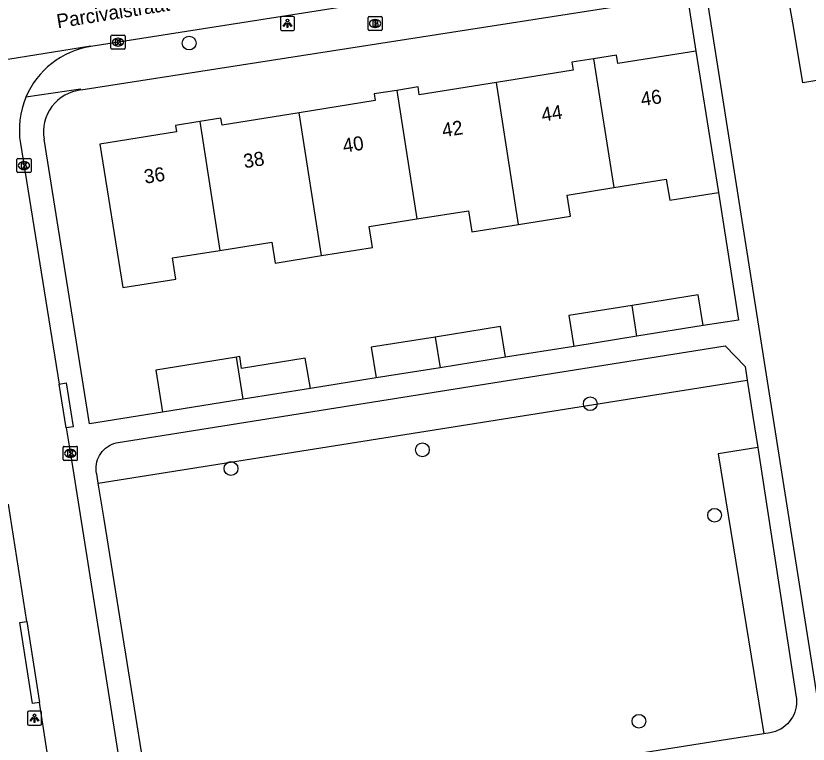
# Model space of a CAD drawing. Extents: x 160077 to 160945, y 386481 to 387498.
# Drawn here: x 160528.9 to 160585.2, y 387094.6 to 387146.3 of the extents above; entities that cross this region are included whole.
import ezdxf

# ---------------------------------------------------------------- set-up
doc = ezdxf.new("R2010")
doc.units = 0
for name, color, linetype in [('IMGEO_Boom', 7, 'Continuous'), ('IMGEO_Brandkraan', 7, 'Continuous'), ('IMGEO_Groenvoorziening', 7, 'Continuous'), ('IMGEO_Kolk', 7, 'Continuous'), ('IMGEO_Lichtpunt', 7, 'Continuous'), ('IMGEO_Openbare_ruimte_label', 7, 'Continuous'), ('IMGEO_Pand', 7, 'Continuous'), ('IMGEO_Pand_nummerreeks', 7, 'Continuous'), ('IMGEO_Rijbaan_lokaal_open', 7, 'Continuous'), ('IMGEO_Voetpad_open', 7, 'Continuous')]:
    doc.layers.add(name, color=color, linetype=linetype)

msp = doc.modelspace()

# ---------------------------------------------------------------- linework, layer by layer
at = {"layer": 'IMGEO_Boom'}
for centre in [(160541.197, 387144.403), (160569.693, 387118.779), (160557.764, 387115.499), (160544.169, 387114.171), (160578.519, 387110.85), (160573.146, 387096.211)]:
    msp.add_circle(centre, 0.489, dxfattribs=at)
at = {"layer": 'IMGEO_Brandkraan'}
for p, q in [((160553.981, 387146.294), (160554.833, 387146.294)), ((160553.906, 387145.368), (160553.906, 387146.22)), ((160554.394, 387146.074), (160554.419, 387146.074)), ((160554.907, 387146.22), (160554.907, 387145.368)), ((160554.833, 387145.294), (160553.981, 387145.294)), ((160554.417, 387145.514), (160554.392, 387145.514))]:
    msp.add_line(p, q, dxfattribs=at)
for points in [[(160553.981, 387146.294), (160554.833, 387146.294)], [(160553.906, 387145.368), (160553.906, 387146.22)], [(160554.254, 387145.994), (160554.254, 387145.594), (160554.467, 387145.594)], [(160554.485, 387145.994), (160554.254, 387145.994)], [(160554.433, 387145.913), (160554.379, 387145.913), (160554.379, 387145.837)], [(160554.379, 387145.837), (160554.432, 387145.837)], [(160554.441, 387145.761), (160554.379, 387145.761), (160554.379, 387145.68)], [(160554.907, 387146.22), (160554.907, 387145.368)], [(160554.833, 387145.294), (160553.981, 387145.294)], [(160554.379, 387145.68), (160554.441, 387145.68)]]:
    msp.add_lwpolyline(points, dxfattribs=at)
for centre, radius, start, end in [((160553.983, 387146.218), 0.0765, 91.552, 178.448), ((160553.983, 387146.218), 0.0765, 91.552, 178.448), ((160554.831, 387146.218), 0.0765, 1.552, 88.448), ((160554.831, 387146.218), 0.0765, 1.552, 88.448), ((160554.434, 387145.875), 0.0379, 267.8285, 90.9355), ((160554.442, 387145.72), 0.0404, 269.8759, 90.5077), ((160554.489, 387145.849), 0.145, 59.4692, 91.5367), ((160554.514, 387145.896), 0.0922, 285.5137, 58.1501), ((160554.519, 387145.704), 0.105, 301.3115, 78.989), ((160553.983, 387145.37), 0.0765, 181.552, 268.448), ((160553.983, 387145.37), 0.0765, 181.552, 268.448), ((160554.473, 387145.845), 0.251, 268.6676, 293.5347), ((160554.831, 387145.37), 0.0765, 271.552, 358.448), ((160554.831, 387145.37), 0.0765, 271.552, 358.448)]:
    msp.add_arc(centre, radius, start, end, dxfattribs=at)
for centre, major_axis, ratio, start_param, end_param in [((160554.393, 387145.794), (-0.387, 0.002), 0.722429, 4.712389, 7.853982), ((160554.418, 387145.794), (-0.39, 0.002), 0.717154, 1.570796, 4.712389)]:
    msp.add_ellipse(centre, major_axis=major_axis, ratio=ratio, start_param=start_param, end_param=end_param, dxfattribs=at)
at = {"layer": 'IMGEO_Groenvoorziening'}
for points in [[(160534.737, 387113.131), (160580.846, 387120.446)], [(160581.584, 387115.663), (160578.776, 387115.218), (160582.014, 387095.328)]]:
    msp.add_lwpolyline(points, dxfattribs=at)
at = {"layer": 'IMGEO_Kolk'}
for p, q in [((160535.642, 387144.042), (160535.642, 387144.894)), ((160535.717, 387144.968), (160536.569, 387144.968)), ((160536.13, 387144.748), (160536.155, 387144.748)), ((160536.643, 387144.894), (160536.643, 387144.042)), ((160536.153, 387144.188), (160536.128, 387144.188)), ((160536.569, 387143.968), (160535.717, 387143.968)), ((160529.037, 387136.199), (160529.889, 387136.199)), ((160528.962, 387135.273), (160528.962, 387136.125)), ((160529.45, 387135.979), (160529.475, 387135.979)), ((160529.963, 387136.125), (160529.963, 387135.273)), ((160529.889, 387135.199), (160529.037, 387135.199)), ((160529.473, 387135.419), (160529.448, 387135.419)), ((160532.253, 387114.822), (160532.253, 387115.674)), ((160532.328, 387115.748), (160533.18, 387115.748)), ((160532.741, 387115.528), (160532.766, 387115.528)), ((160533.254, 387115.674), (160533.254, 387114.822)), ((160533.18, 387114.748), (160532.328, 387114.748)), ((160532.764, 387114.968), (160532.739, 387114.968))]:
    msp.add_line(p, q, dxfattribs=at)
for points in [[(160535.642, 387144.042), (160535.642, 387144.894)], [(160535.717, 387144.968), (160536.569, 387144.968)], [(160535.963, 387144.668), (160536.086, 387144.668), (160536.086, 387144.517), (160536.216, 387144.668), (160536.38, 387144.668), (160536.234, 387144.517), (160536.387, 387144.268), (160536.235, 387144.268), (160536.15, 387144.432), (160536.086, 387144.365), (160536.086, 387144.268), (160535.963, 387144.268), (160535.963, 387144.668)], [(160536.643, 387144.894), (160536.643, 387144.042)], [(160536.569, 387143.968), (160535.717, 387143.968)], [(160529.037, 387136.199), (160529.889, 387136.199)], [(160528.962, 387135.273), (160528.962, 387136.125)], [(160529.283, 387135.899), (160529.406, 387135.899), (160529.406, 387135.748), (160529.536, 387135.899), (160529.7, 387135.899), (160529.554, 387135.748), (160529.707, 387135.499), (160529.555, 387135.499), (160529.47, 387135.663), (160529.406, 387135.596), (160529.406, 387135.499), (160529.283, 387135.499), (160529.283, 387135.899)], [(160529.963, 387136.125), (160529.963, 387135.273)], [(160529.889, 387135.199), (160529.037, 387135.199)], [(160532.253, 387114.822), (160532.253, 387115.674)], [(160532.328, 387115.748), (160533.18, 387115.748)], [(160532.574, 387115.448), (160532.697, 387115.448), (160532.697, 387115.297), (160532.827, 387115.448), (160532.991, 387115.448), (160532.845, 387115.297), (160532.998, 387115.048), (160532.846, 387115.048), (160532.761, 387115.212), (160532.697, 387115.145), (160532.697, 387115.048), (160532.574, 387115.048), (160532.574, 387115.448)], [(160533.254, 387115.674), (160533.254, 387114.822)], [(160533.18, 387114.748), (160532.328, 387114.748)]]:
    msp.add_lwpolyline(points, dxfattribs=at)
for centre, start, end in [((160535.719, 387144.892), 91.552, 178.448), ((160535.719, 387144.892), 91.552, 178.448), ((160536.567, 387144.892), 1.552, 88.448), ((160536.567, 387144.892), 1.552, 88.448), ((160535.719, 387144.044), 181.552, 268.448), ((160535.719, 387144.044), 181.552, 268.448), ((160536.567, 387144.044), 271.552, 358.448), ((160536.567, 387144.044), 271.552, 358.448), ((160529.039, 387136.123), 91.552, 178.448), ((160529.039, 387136.123), 91.552, 178.448), ((160529.887, 387136.123), 1.552, 88.448), ((160529.887, 387136.123), 1.552, 88.448), ((160529.039, 387135.275), 181.552, 268.448), ((160529.039, 387135.275), 181.552, 268.448), ((160529.887, 387135.275), 271.552, 358.448), ((160529.887, 387135.275), 271.552, 358.448), ((160532.33, 387115.672), 91.552, 178.448), ((160532.33, 387115.672), 91.552, 178.448), ((160533.178, 387115.672), 1.552, 88.448), ((160533.178, 387115.672), 1.552, 88.448), ((160532.33, 387114.824), 181.552, 268.448), ((160532.33, 387114.824), 181.552, 268.448), ((160533.178, 387114.824), 271.552, 358.448), ((160533.178, 387114.824), 271.552, 358.448)]:
    msp.add_arc(centre, 0.0765, start, end, dxfattribs=at)
for centre, major_axis, ratio, start_param, end_param in [((160536.129, 387144.468), (-0.387, 0.002), 0.722429, 4.712389, 7.853982), ((160536.154, 387144.468), (-0.39, 0.002), 0.717154, 1.570796, 4.712389), ((160529.449, 387135.699), (-0.387, 0.002), 0.722429, 4.712389, 7.853982), ((160529.474, 387135.699), (-0.39, 0.002), 0.717154, 1.570796, 4.712389), ((160532.74, 387115.248), (-0.387, 0.002), 0.722429, 4.712389, 7.853982), ((160532.765, 387115.248), (-0.39, 0.002), 0.717154, 1.570796, 4.712389)]:
    msp.add_ellipse(centre, major_axis=major_axis, ratio=ratio, start_param=start_param, end_param=end_param, dxfattribs=at)
at = {"layer": 'IMGEO_Lichtpunt'}
for p, q in [((160548.582, 387146.302), (160547.774, 387146.302)), ((160548.582, 387146.302), (160547.774, 387146.302)), ((160547.68, 387146.207), (160547.68, 387145.4)), ((160547.68, 387146.207), (160547.68, 387145.4)), ((160548.676, 387145.4), (160548.676, 387146.207)), ((160548.676, 387145.4), (160548.676, 387146.207)), ((160547.774, 387145.306), (160548.582, 387145.306)), ((160547.774, 387145.306), (160548.582, 387145.306)), ((160529.709, 387096.837), (160529.709, 387096.03)), ((160529.709, 387096.837), (160529.709, 387096.03)), ((160530.611, 387096.932), (160529.803, 387096.932)), ((160530.611, 387096.932), (160529.803, 387096.932)), ((160530.705, 387096.03), (160530.705, 387096.837)), ((160530.705, 387096.03), (160530.705, 387096.837)), ((160529.803, 387095.936), (160530.611, 387095.936)), ((160529.803, 387095.936), (160530.611, 387095.936))]:
    msp.add_line(p, q, dxfattribs=at)
for points in [[(160548.054, 387145.871), (160548.093, 387145.843), (160547.905, 387145.581), (160547.867, 387145.608), (160548.054, 387145.871)], [(160548.156, 387145.823), (160548.203, 387145.823), (160548.203, 387145.501), (160548.156, 387145.501), (160548.156, 387145.823)], [(160548.266, 387145.843), (160548.304, 387145.87), (160548.491, 387145.608), (160548.452, 387145.58), (160548.266, 387145.843)], [(160530.083, 387096.501), (160530.122, 387096.473), (160529.934, 387096.211), (160529.896, 387096.238), (160530.083, 387096.501)], [(160530.185, 387096.453), (160530.232, 387096.453), (160530.232, 387096.131), (160530.185, 387096.131), (160530.185, 387096.453)], [(160530.295, 387096.473), (160530.333, 387096.5), (160530.52, 387096.238), (160530.481, 387096.21), (160530.295, 387096.473)]]:
    msp.add_lwpolyline(points, dxfattribs=at)
for centre in [(160548.179, 387146.005), (160530.208, 387096.635)]:
    msp.add_circle(centre, 0.0994, dxfattribs=at)
for centre, start, end in [((160547.774, 387146.207), 90, 180), ((160547.774, 387146.207), 90, 180), ((160548.582, 387146.207), 0, 90), ((160548.582, 387146.207), 0, 90), ((160547.774, 387145.4), 180, 270), ((160547.774, 387145.4), 180, 270), ((160548.582, 387145.4), 270, 0), ((160548.582, 387145.4), 270, 360), ((160529.803, 387096.837), 90, 180), ((160529.803, 387096.837), 90, 180), ((160530.611, 387096.837), 0, 90), ((160530.611, 387096.837), 0, 90), ((160529.803, 387096.03), 180, 270), ((160529.803, 387096.03), 180, 270), ((160530.611, 387096.03), 270, 0), ((160530.611, 387096.03), 270, 360)]:
    msp.add_arc(centre, 0.0946, start, end, dxfattribs=at)
at = {"layer": 'IMGEO_Pand'}
for points in [[(160589.356, 387138.611), (160588.739, 387142.241), (160584.795, 387141.57), (160584.139, 387145.429), (160583.82, 387147.304), (160592.221, 387148.726), (160592.068, 387149.63), (160597.838, 387150.607), (160598.182, 387148.576), (160598.197, 387148.49), (160597.3, 387148.338), (160597.413, 387147.677), (160597.202, 387147.641), (160597.776, 387144.255), (160600.083, 387144.098), (160600.707, 387140.417)], [(160577.19, 387143.831), (160571.641, 387142.943), (160571.543, 387143.552), (160569.927, 387143.293)], [(160577.19, 387143.831), (160578.799, 387133.783)], [(160569.927, 387143.293), (160568.385, 387143.046), (160568.475, 387142.486), (160563.021, 387141.612)], [(160569.927, 387143.293), (160571.357, 387134.136)], [(160563.021, 387141.612), (160557.546, 387140.735), (160557.458, 387141.284), (160555.942, 387141.041)], [(160564.597, 387131.519), (160563.021, 387141.612)], [(160555.942, 387141.041), (160554.346, 387140.785), (160554.42, 387140.319), (160549.02, 387139.454)], [(160555.942, 387141.041), (160557.368, 387131.906)], [(160549.02, 387139.454), (160543.532, 387138.575), (160543.454, 387139.065), (160541.949, 387138.824)], [(160550.605, 387129.298), (160549.02, 387139.454)], [(160541.949, 387138.824), (160540.233, 387138.549), (160540.306, 387138.093), (160534.855, 387137.22), (160536.486, 387127.037), (160540.247, 387127.636), (160540.008, 387129.138), (160543.378, 387129.675)], [(160541.949, 387138.824), (160543.378, 387129.675)], [(160571.357, 387134.136), (160575.091, 387134.731), (160575.331, 387133.23), (160578.799, 387133.783)], [(160564.597, 387131.519), (160568.278, 387132.105), (160568.039, 387133.607), (160571.357, 387134.136)], [(160557.368, 387131.906), (160561.046, 387132.492), (160561.286, 387130.991), (160564.597, 387131.519)], [(160550.605, 387129.298), (160554.231, 387129.876), (160553.994, 387131.368), (160557.368, 387131.906)], [(160543.378, 387129.675), (160547.06, 387130.262), (160547.298, 387128.771), (160550.605, 387129.298)], [(160577.698, 387124.323), (160577.349, 387126.505), (160572.667, 387125.755)], [(160572.667, 387125.755), (160568.166, 387125.034), (160568.515, 387122.853)], [(160573.008, 387123.572), (160572.667, 387125.755)], [(160577.698, 387124.323), (160573.008, 387123.572)], [(160563.668, 387122.075), (160563.319, 387124.257), (160558.678, 387123.514)], [(160558.678, 387123.514), (160554.136, 387122.786), (160554.485, 387120.605)], [(160558.678, 387123.514), (160559.019, 387121.331)], [(160573.008, 387123.572), (160568.515, 387122.853)], [(160544.563, 387122.085), (160538.833, 387121.167), (160539.312, 387118.175)], [(160549.828, 387119.859), (160549.446, 387122.007), (160544.923, 387121.282), (160544.788, 387122.121), (160544.563, 387122.085)], [(160545.031, 387119.091), (160544.563, 387122.085)], [(160563.668, 387122.075), (160559.019, 387121.331)], [(160559.019, 387121.331), (160554.485, 387120.605)], [(160549.828, 387119.859), (160545.031, 387119.091)], [(160545.031, 387119.091), (160539.312, 387118.175)]]:
    msp.add_lwpolyline(points, dxfattribs=at)
at = {"layer": 'IMGEO_Rijbaan_lokaal_open'}
for points in [[(160562.894, 387148.69), (160560.487, 387148.307), (160534.212, 387144.165)], [(160517.975, 387141.6), (160534.205, 387144.195), (160534.212, 387144.165)], [(160529.209, 387137.267), (160531.96, 387120.174)], [(160532.46, 387117.066), (160531.96, 387120.174)], [(160532.46, 387117.066), (160532.759, 387115.209), (160537.214, 387087.127)], [(160529.664, 387103.302), (160528.364, 387111.64)], [(160529.664, 387103.302), (160530.562, 387097.546)], [(160532.066, 387087.893), (160530.562, 387097.546)]]:
    msp.add_lwpolyline(points, dxfattribs=at)
for centre, radius, start, end in [((160535.149, 387138.221), 6.017, 98.9625, 157.23), ((160535.148, 387138.223), 6.015, 157.2384, 189.1435)]:
    msp.add_arc(centre, radius, start, end, dxfattribs=at)
at = {"layer": 'IMGEO_Voetpad_open'}
for points in [[(160608.755, 387093.814), (160587.001, 387090.478), (160577.918, 387148.033)], [(160533.512, 387141.07), (160576.566, 387147.818)], [(160576.566, 387147.818), (160577.19, 387143.831)], [(160533.512, 387141.07), (160533.487, 387141.133), (160529.601, 387140.55)], [(160539.312, 387118.175), (160534.118, 387117.343), (160530.896, 387137.578)], [(160578.799, 387133.783), (160580.214, 387124.725), (160577.698, 387124.323)], [(160534.737, 387113.131), (160534.629, 387113.8), (160534.626, 387113.814), (160534.601, 387113.979), (160534.591, 387114.146), (160534.595, 387114.313), (160534.615, 387114.478), (160534.649, 387114.642), (160534.698, 387114.802), (160534.76, 387114.956), (160534.837, 387115.105), (160534.926, 387115.246), (160535.028, 387115.378), (160535.141, 387115.501), (160535.264, 387115.614), (160535.397, 387115.715), (160535.539, 387115.803), (160535.687, 387115.879), (160535.842, 387115.941), (160536.002, 387115.989), (160536.166, 387116.022), (160579.265, 387122.896), (160580.694, 387121.428), (160580.846, 387120.446)], [(160568.515, 387122.853), (160563.668, 387122.075)], [(160554.485, 387120.605), (160549.828, 387119.859)], [(160580.846, 387120.446), (160581.243, 387117.876), (160581.584, 387115.663)], [(160531.96, 387120.174), (160532.453, 387120.252), (160532.953, 387117.144), (160532.46, 387117.066)], [(160581.584, 387115.663), (160584.322, 387097.934), (160584.334, 387097.843), (160584.346, 387097.644), (160584.341, 387097.445), (160584.318, 387097.246), (160584.277, 387097.051), (160584.219, 387096.86), (160584.144, 387096.675), (160584.053, 387096.498), (160583.946, 387096.329), (160583.825, 387096.17), (160583.69, 387096.023), (160583.543, 387095.889), (160583.384, 387095.768), (160583.215, 387095.662), (160583.037, 387095.572), (160582.852, 387095.497), (160582.66, 387095.44), (160582.465, 387095.4), (160582.014, 387095.328)], [(160582.014, 387095.328), (160579.446, 387094.921), (160540.468, 387088.738), (160540.394, 387088.728), (160540.234, 387088.717), (160540.074, 387088.72), (160539.915, 387088.737), (160539.758, 387088.769), (160539.604, 387088.814), (160539.455, 387088.873), (160539.312, 387088.945), (160539.176, 387089.029), (160539.048, 387089.126), (160538.929, 387089.233), (160538.82, 387089.351), (160538.722, 387089.478), (160538.636, 387089.613), (160538.562, 387089.755), (160538.502, 387089.903), (160538.454, 387090.056), (160538.421, 387090.213), (160535.149, 387110.564), (160534.737, 387113.131)], [(160530.562, 387097.546), (160530.068, 387097.471), (160529.17, 387103.227), (160529.664, 387103.302)]]:
    msp.add_lwpolyline(points, dxfattribs=at)
msp.add_arc((160533.841, 387138.097), 2.991, 96.3202, 190.0031, dxfattribs=at)

# ---------------------------------------------------------------- texts
at = {"layer": 'IMGEO_Openbare_ruimte_label'}
msp.add_text('Parcivalstraat', height=1, rotation=9.0292, dxfattribs=at).set_placement((160531.866, 387145.449))
at = {"layer": 'IMGEO_Pand_nummerreeks'}
for s, p in [('46', (160573.352, 387139.912)), ('44', (160566.296, 387138.81)), ('42', (160559.237, 387137.707)), ('40', (160552.187, 387136.606)), ('38', (160545.131, 387135.504)), ('36', (160538.072, 387134.403))]:
    msp.add_text(s, height=1, rotation=8.8756, dxfattribs=at).set_placement(p)

doc.saveas('drawing.dxf')
